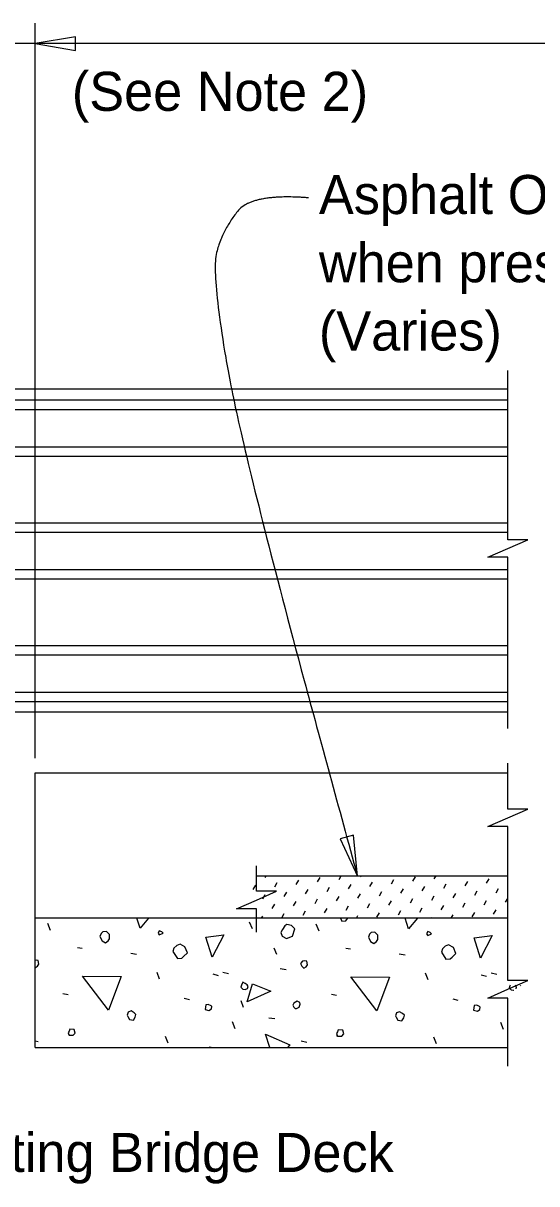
# Model space of a CAD drawing. Extents: x 21516.9 to 21586.2, y 56154.4 to 56193.6.
# Drawn here: x 21530.64 to 21533.29, y 56169.85 to 56175.84 of the extents above; entities that cross this region are included whole.
import ezdxf

# ---------------------------------------------------------------- set-up
doc = ezdxf.new("R2010")
doc.units = 0
for name, color, linetype in [('AdhocPoint_dp', 7, 'Continuous'), ('Patterning', 7, 'Continuous'), ('PlotBorder_dp', 7, 'Continuous'), ('SheetBorder_dp', 7, 'Continuous'), ('TextMisc', 7, 'Continuous')]:
    doc.layers.add(name, color=color, linetype=linetype)

msp = doc.modelspace()

# ---------------------------------------------------------------- linework, layer by layer
at = {"layer": 'AdhocPoint_dp'}
for p, q in [((21530.7049, 56170.5532), (21530.7049, 56171.9698)), ((21530.7049, 56171.9698), (21533.1431, 56171.9698)), ((21531.8465, 56171.4387), (21533.1431, 56171.4387)), ((21533.1431, 56171.2198), (21530.7049, 56171.2198)), ((21530.7049, 56170.5532), (21533.1431, 56170.5532))]:
    msp.add_line(p, q, dxfattribs=at)
at = {"layer": 'Patterning'}
for p, q in [((21531.8923, 56171.4301), (21531.8973, 56171.4387)), ((21532.273, 56171.4202), (21532.2838, 56171.4387)), ((21532.3837, 56171.4331), (21532.3869, 56171.4387)), ((21532.7644, 56171.4232), (21532.7734, 56171.4387)), ((21532.875, 56171.4361), (21532.8765, 56171.4387)), ((21531.8305, 56171.3683), (21531.8435, 56171.3907)), ((21531.9411, 56171.3813), (21531.9541, 56171.4037)), ((21532.0518, 56171.3942), (21532.0647, 56171.4166)), ((21532.1624, 56171.4072), (21532.1754, 56171.4296)), ((21532.2112, 56171.3584), (21532.2242, 56171.3808)), ((21532.3219, 56171.3713), (21532.3348, 56171.3937)), ((21532.4325, 56171.3843), (21532.4455, 56171.4067)), ((21532.5431, 56171.3973), (21532.5561, 56171.4196)), ((21532.6538, 56171.4102), (21532.6667, 56171.4326)), ((21532.7026, 56171.3614), (21532.7156, 56171.3838)), ((21532.8132, 56171.3743), (21532.8262, 56171.3967)), ((21532.9239, 56171.3873), (21532.9368, 56171.4097)), ((21533.0345, 56171.4003), (21533.0475, 56171.4227)), ((21531.8793, 56171.3195), (21531.8923, 56171.3419)), ((21531.99, 56171.3324), (21532.0029, 56171.3548)), ((21532.1006, 56171.3454), (21532.1136, 56171.3678)), ((21532.1494, 56171.2966), (21532.1624, 56171.319)), ((21532.2601, 56171.3095), (21532.273, 56171.3319)), ((21532.3707, 56171.3225), (21532.3837, 56171.3449)), ((21532.4813, 56171.3355), (21532.4943, 56171.3578)), ((21532.592, 56171.3484), (21532.6049, 56171.3708)), ((21532.6408, 56171.2996), (21532.6538, 56171.322)), ((21532.7514, 56171.3125), (21532.7644, 56171.3349)), ((21532.8621, 56171.3255), (21532.875, 56171.3479)), ((21532.9727, 56171.3385), (21532.9857, 56171.3609)), ((21533.0833, 56171.3514), (21533.0963, 56171.3738)), ((21533.1322, 56171.3026), (21533.1431, 56171.3215)), ((21531.9282, 56171.2706), (21531.9411, 56171.293)), ((21532.0388, 56171.2836), (21532.0518, 56171.306)), ((21532.1983, 56171.2477), (21532.2112, 56171.2701)), ((21532.3089, 56171.2607), (21532.3219, 56171.2831)), ((21532.4195, 56171.2737), (21532.4325, 56171.296)), ((21532.5302, 56171.2866), (21532.5431, 56171.309)), ((21532.579, 56171.2378), (21532.592, 56171.2602)), ((21532.6896, 56171.2507), (21532.7026, 56171.2731)), ((21532.8003, 56171.2637), (21532.8132, 56171.2861)), ((21532.9109, 56171.2767), (21532.9239, 56171.2991)), ((21533.0215, 56171.2896), (21533.0345, 56171.312)), ((21533.0704, 56171.2408), (21533.0833, 56171.2632)), ((21531.8257, 56171.1649), (21531.8116, 56171.2002)), ((21531.8727, 56171.2198), (21531.8793, 56171.2312)), ((21531.977, 56171.2218), (21531.99, 56171.2442)), ((21532.0876, 56171.2348), (21532.1006, 56171.2572)), ((21532.2592, 56171.2198), (21532.2601, 56171.2213)), ((21532.3623, 56171.2198), (21532.3707, 56171.2343)), ((21532.4684, 56171.2248), (21532.4813, 56171.2472)), ((21532.7488, 56171.2198), (21532.7514, 56171.2243)), ((21532.852, 56171.2198), (21532.8621, 56171.2373)), ((21532.9597, 56171.2278), (21532.9727, 56171.2502)), ((21530.7851, 56171.1567), (21530.771, 56171.192)), ((21532.1698, 56171.1531), (21532.1556, 56171.1885)), ((21530.923, 56171.0683), (21530.9477, 56171.0647)), ((21531.1988, 56171.04), (21531.2288, 56171.0347)), ((21531.9512, 56171.0323), (21531.9388, 56171.0659)), ((21532.3077, 56171.0647), (21532.3324, 56171.0612)), ((21532.5834, 56171.0365), (21532.6135, 56171.0312)), ((21531.97, 56170.9604), (21532.0001, 56170.9551)), ((21531.3473, 56170.9056), (21531.3349, 56170.9392)), ((21531.6213, 56170.9322), (21531.6495, 56170.9251)), ((21531.6737, 56170.9421), (21531.702, 56170.9351)), ((21532.7319, 56170.9021), (21532.7196, 56170.9357)), ((21533.0059, 56170.9286), (21533.0342, 56170.9216)), ((21533.0583, 56170.9386), (21533.0866, 56170.9315)), ((21530.8487, 56170.8314), (21530.8753, 56170.8261)), ((21531.4745, 56170.8066), (21531.5011, 56170.8013)), ((21531.7797, 56170.7595), (21531.7674, 56170.7931)), ((21532.2334, 56170.8279), (21532.2599, 56170.8226)), ((21532.8592, 56170.8031), (21532.8857, 56170.7978)), ((21531.7373, 56170.6499), (21531.7232, 56170.6853)), ((21531.9099, 56170.7059), (21531.9417, 56170.7023)), ((21533.122, 56170.6464), (21533.1078, 56170.6818)), ((21531.3915, 56170.5751), (21531.3773, 56170.6104)), ((21532.7761, 56170.5715), (21532.762, 56170.6069)), ((21530.7049, 56170.588), (21530.7215, 56170.5839)), ((21532.0779, 56170.5874), (21532.1061, 56170.5804))]:
    msp.add_line(p, q, dxfattribs=at)
for points in [[(21531.2465, 56171.169), (21531.23, 56171.2198)], [(21531.2895, 56171.2198), (21531.2465, 56171.169)], [(21532.2797, 56171.2198), (21532.2882, 56171.2044), (21532.3077, 56171.2062), (21532.3165, 56171.2185), (21532.3166, 56171.2198)], [(21532.6312, 56171.1655), (21532.6135, 56171.2198)], [(21532.6771, 56171.2198), (21532.6312, 56171.1655)], [(21531.0397, 56171.1248), (21531.0503, 56171.1036), (21531.068, 56171.093), (21531.0821, 56171.1036), (21531.0892, 56171.1142), (21531.0892, 56171.1355), (21531.0733, 56171.1514), (21531.0538, 56171.1496), (21531.045, 56171.1408), (21531.0397, 56171.1248)], [(21531.3455, 56171.1337), (21531.3649, 56171.1425), (21531.3579, 56171.1496), (21531.3455, 56171.1549), (21531.3402, 56171.1425), (21531.3455, 56171.1337)], [(21531.9795, 56171.1278), (21532.0025, 56171.1154), (21532.0325, 56171.1278), (21532.0449, 56171.1649), (21532.0272, 56171.1826), (21532.0042, 56171.1879), (21531.9936, 56171.1808), (21531.9813, 56171.1613), (21531.9724, 56171.1454), (21531.9795, 56171.1278)], [(21532.4243, 56171.1213), (21532.435, 56171.1001), (21532.4526, 56171.0895), (21532.4668, 56171.1001), (21532.4738, 56171.1107), (21532.4738, 56171.1319), (21532.4579, 56171.1478), (21532.4385, 56171.1461), (21532.4296, 56171.1372), (21532.4243, 56171.1213)], [(21532.7302, 56171.1301), (21532.7496, 56171.139), (21532.7425, 56171.1461), (21532.7302, 56171.1514), (21532.7249, 56171.139), (21532.7302, 56171.1301)], [(21531.4162, 56171.0488), (21531.4392, 56171.0117), (21531.4622, 56171.0135), (21531.471, 56171.0223), (21531.4904, 56171.0418), (21531.4781, 56171.0718), (21531.4533, 56171.086), (21531.4356, 56171.0789), (21531.4215, 56171.0647), (21531.4162, 56171.0488)], [(21531.6189, 56171.0182), (21531.5853, 56171.1225), (21531.679, 56171.1348), (21531.6189, 56171.0182)], [(21532.8009, 56171.0453), (21532.8239, 56171.0082), (21532.8468, 56171.0099), (21532.8557, 56171.0188), (21532.8751, 56171.0382), (21532.8628, 56171.0683), (21532.838, 56171.0824), (21532.8203, 56171.0753), (21532.8062, 56171.0612), (21532.8009, 56171.0453)], [(21533.0035, 56171.0146), (21532.97, 56171.1189), (21533.0637, 56171.1313), (21533.0035, 56171.0146)], [(21530.7049, 56170.9682), (21530.7073, 56170.9657), (21530.7179, 56170.9728), (21530.725, 56170.9834), (21530.7215, 56171.0011), (21530.7126, 56171.0029), (21530.7049, 56171.0018)], [(21532.0814, 56170.9728), (21532.092, 56170.9622), (21532.1026, 56170.9693), (21532.1097, 56170.9799), (21532.1061, 56170.9976), (21532.0973, 56170.9993), (21532.0849, 56170.9976), (21532.0743, 56170.987), (21532.0814, 56170.9728)], [(21531.0839, 56170.7448), (21530.9495, 56170.9216), (21531.1493, 56170.9198), (21531.0839, 56170.7448)], [(21532.4685, 56170.7412), (21532.3342, 56170.918), (21532.5339, 56170.9162), (21532.4685, 56170.7412)], [(21531.7762, 56170.8538), (21531.7886, 56170.852), (21531.8009, 56170.8573), (21531.8045, 56170.8679), (21531.7992, 56170.8767), (21531.7886, 56170.8838), (21531.7762, 56170.8891), (21531.7691, 56170.875), (21531.7656, 56170.8644), (21531.7762, 56170.8538)], [(21531.7986, 56170.789), (21531.8268, 56170.8809), (21531.9205, 56170.8438), (21531.7986, 56170.789)], [(21533.1552, 56170.8742), (21533.1538, 56170.8714), (21533.1503, 56170.8608), (21533.1609, 56170.8502)], [(21533.1609, 56170.8502), (21533.1733, 56170.8484), (21533.1751, 56170.8493)], [(21533.1865, 56170.8562), (21533.1892, 56170.8644), (21533.1839, 56170.8732), (21533.1823, 56170.8742)], [(21533.2094, 56170.8704), (21533.2106, 56170.8742)], [(21532.046, 56170.7536), (21532.0531, 56170.7536), (21532.0673, 56170.7607), (21532.0726, 56170.7766), (21532.0708, 56170.7854), (21532.0566, 56170.7925), (21532.039, 56170.7819), (21532.0354, 56170.7713), (21532.039, 56170.7607), (21532.046, 56170.7536)], [(21531.1829, 56170.713), (21531.1917, 56170.697), (21531.2129, 56170.6935), (21531.2217, 56170.7094), (21531.2253, 56170.7236), (21531.2164, 56170.7324), (21531.2005, 56170.7412), (21531.1846, 56170.7359), (21531.1793, 56170.72), (21531.1829, 56170.713)], [(21531.5824, 56170.7483), (21531.6018, 56170.743), (21531.6142, 56170.7518), (21531.616, 56170.7642), (21531.6124, 56170.7678), (21531.5983, 56170.7748), (21531.5859, 56170.7731), (21531.5841, 56170.7607), (21531.5824, 56170.7483)], [(21532.5675, 56170.7094), (21532.5764, 56170.6935), (21532.5976, 56170.69), (21532.6064, 56170.7059), (21532.61, 56170.72), (21532.6011, 56170.7289), (21532.5852, 56170.7377), (21532.5693, 56170.7324), (21532.564, 56170.7165), (21532.5675, 56170.7094)], [(21532.967, 56170.7448), (21532.9865, 56170.7395), (21532.9989, 56170.7483), (21533.0006, 56170.7607), (21532.9971, 56170.7642), (21532.983, 56170.7713), (21532.9706, 56170.7695), (21532.9688, 56170.7571), (21532.967, 56170.7448)], [(21530.8806, 56170.6157), (21530.9018, 56170.6157), (21530.9124, 56170.6263), (21530.9071, 56170.6458), (21530.8841, 56170.6475), (21530.8806, 56170.6369), (21530.8753, 56170.6281), (21530.8806, 56170.6157), (21530.877, 56170.6193)], [(21531.9152, 56170.5532), (21531.8929, 56170.6217), (21532.0184, 56170.5669), (21532.0068, 56170.5532)], [(21532.2652, 56170.6122), (21532.2865, 56170.6122), (21532.2971, 56170.6228), (21532.2918, 56170.6422), (21532.2688, 56170.644), (21532.2652, 56170.6334), (21532.2599, 56170.6246), (21532.2652, 56170.6122), (21532.2617, 56170.6157)], [(21531.6131, 56170.5532), (21531.6065, 56170.5545), (21531.6025, 56170.5532)]]:
    msp.add_lwpolyline(points, dxfattribs=at)
at = {"layer": 'PlotBorder_dp'}
for p, q in [((21530.7049, 56172.0461), (21530.7049, 56175.8373)), ((21534.5904, 56175.7323), (21529.056, 56175.7323))]:
    msp.add_line(p, q, dxfattribs=at)
for points in [[(21530.7048, 56175.7323), (21530.9131, 56175.697), (21530.9131, 56175.7676)], [(21532.3683, 56171.4376), (21532.3468, 56171.6477), (21532.2788, 56171.6289)]]:
    msp.add_lwpolyline(points, close=True, dxfattribs=at)
for points in [[(21533.1431, 56172.1993), (21533.1431, 56173.0825), (21533.0398, 56173.0825), (21533.1431, 56173.1275), (21533.2464, 56173.1725), (21533.1431, 56173.1725), (21533.1431, 56174.0455)], [(21533.1431, 56171.2225), (21533.1431, 56171.6925), (21533.0398, 56171.6925), (21533.1431, 56171.7375), (21533.2464, 56171.7825), (21533.1431, 56171.7825), (21533.1431, 56172.0199)], [(21531.8465, 56171.1478), (21531.8465, 56171.2687), (21531.7432, 56171.2687), (21531.8465, 56171.3137), (21531.9498, 56171.3587), (21531.8465, 56171.3587), (21531.8465, 56171.4893)], [(21533.1431, 56170.4574), (21533.1431, 56170.808), (21533.0398, 56170.808), (21533.1431, 56170.853), (21533.2464, 56170.898), (21533.1431, 56170.898), (21533.1431, 56171.2225)]]:
    msp.add_lwpolyline(points, dxfattribs=at)
msp.add_open_spline([(21532.1153, 56174.9363), (21531.824, 56174.9593), (21531.6756, 56174.7751), (21531.6102, 56174.5488), (21531.7957, 56173.5094), (21532.3682, 56171.4376)], degree=2, dxfattribs=at)
at = {"layer": 'TextMisc'}
for p, q in [((21533.1431, 56173.949), (21525.0027, 56173.949)), ((21525.0027, 56173.8935), (21533.1431, 56173.8935)), ((21525.0027, 56173.8452), (21533.1431, 56173.8452)), ((21525.0027, 56173.6524), (21533.1431, 56173.6524)), ((21525.0027, 56173.6042), (21533.1431, 56173.6042)), ((21525.0027, 56173.2602), (21533.1431, 56173.2602)), ((21525.0027, 56173.212), (21533.1431, 56173.212)), ((21525.0027, 56173.0192), (21533.1431, 56173.0192)), ((21525.0027, 56172.9711), (21533.1431, 56172.9711)), ((21525.0027, 56172.6271), (21533.1431, 56172.6271)), ((21525.0027, 56172.5789), (21533.1431, 56172.5789)), ((21525.0027, 56172.3861), (21533.1431, 56172.3861)), ((21525.0027, 56172.3378), (21533.1431, 56172.3378)), ((21533.1431, 56172.2823), (21525.0027, 56172.2823))]:
    msp.add_line(p, q, dxfattribs=at)

# ---------------------------------------------------------------- texts
at = {"layer": 'PlotBorder_dp'}
for s, p in [('Asphalt Overlay', (21532.1691, 56174.8526)), ('when present', (21532.1691, 56174.5006)), ('(Varies)', (21532.1691, 56174.1486))]:
    msp.add_text(s, height=0.2016, dxfattribs=at).set_placement(p)
at = {"layer": 'SheetBorder_dp'}
for s, p in [('(See Note 2)', (21530.8945, 56175.3852)), ('Existing Bridge Deck', (21530.0679, 56169.9106))]:
    msp.add_text(s, height=0.2016, dxfattribs=at).set_placement(p)

doc.saveas('drawing.dxf')
